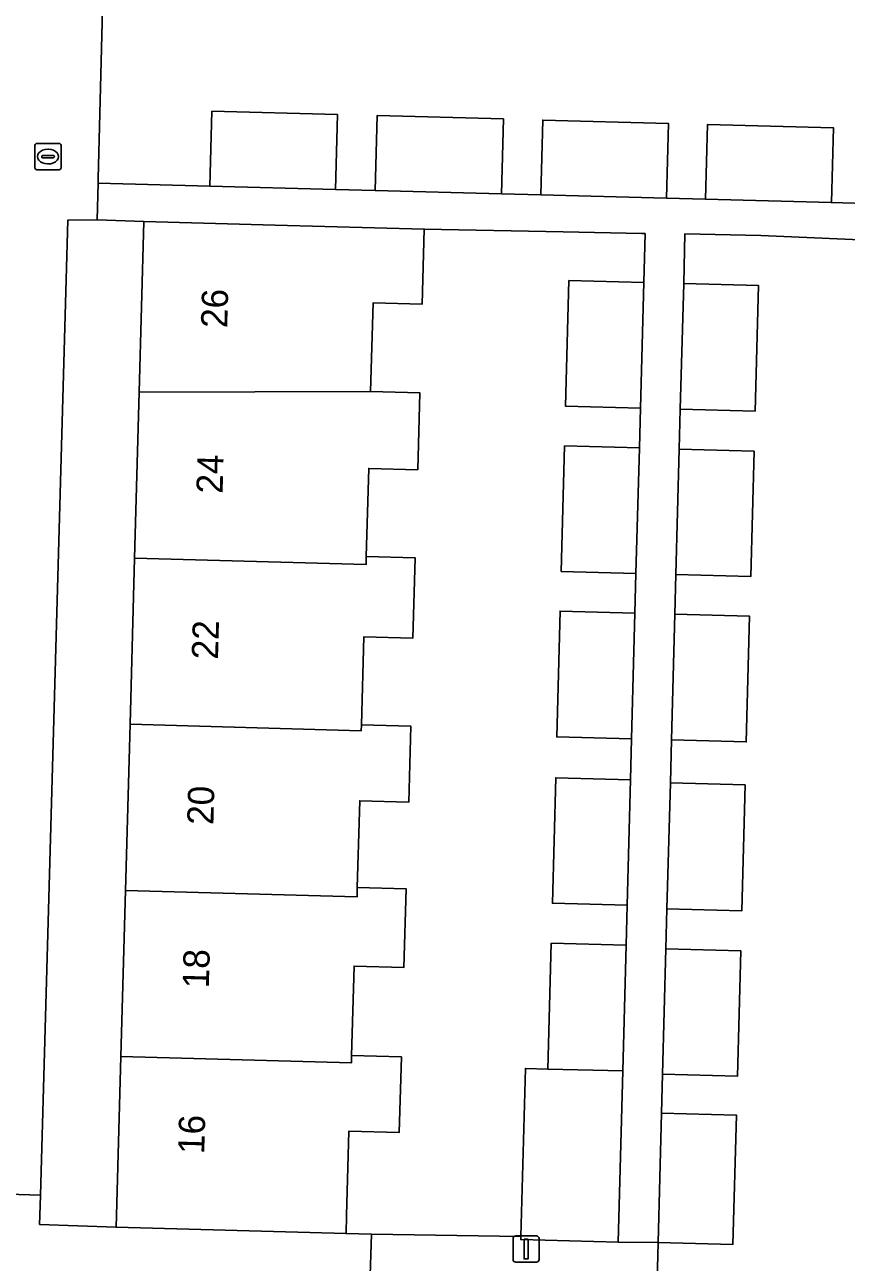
# Model space of a CAD drawing. Extents: x 162082 to 163401, y 388089 to 388636.
# Drawn here: x 162530.44 to 162561.73, y 388248.21 to 388295.36 of the extents above; entities that cross this region are included whole.
import ezdxf

# ---------------------------------------------------------------- set-up
doc = ezdxf.new("R2010")
doc.units = 0
for name, color, linetype in [('IMGEO_Erf', 7, 'Continuous'), ('IMGEO_Lichtmast', 7, 'Continuous'), ('IMGEO_Muur', 7, 'Continuous'), ('IMGEO_Pand', 7, 'Continuous'), ('IMGEO_Pand_nummerreeks', 7, 'Continuous'), ('IMGEO_Rijbaan_lokaal_open', 7, 'Continuous'), ('IMGEO_Rioolput', 7, 'Continuous'), ('IMGEO_Voetpad_open', 7, 'Continuous')]:
    doc.layers.add(name, color=color, linetype=linetype)

msp = doc.modelspace()

# ---------------------------------------------------------------- linework, layer by layer
at = {"layer": 'IMGEO_Erf'}
for points in [[(162533.487, 388299.428), (162533.238, 388289.496), (162533.234, 388289.327), (162537.498, 388289.214), (162537.574, 388292.063), (162542.353, 388291.935), (162542.278, 388289.086), (162543.785, 388289.046), (162543.86, 388291.895), (162548.673, 388291.768), (162548.598, 388288.919), (162550.1, 388288.879), (162550.176, 388291.728), (162554.961, 388291.6), (162554.885, 388288.751), (162556.378, 388288.712), (162556.454, 388291.561), (162561.247, 388291.433), (162561.171, 388288.584), (162562.91, 388288.538)], [(162563.431, 388287.118), (162558.479, 388287.33), (162555.592, 388287.396), (162555.542, 388285.5), (162558.391, 388285.424), (162558.263, 388280.639), (162555.414, 388280.715), (162555.373, 388279.184), (162558.222, 388279.108), (162558.095, 388274.332), (162555.246, 388274.408), (162555.206, 388272.898), (162558.055, 388272.822), (162557.927, 388268.039), (162555.078, 388268.115), (162555.034, 388266.473), (162557.883, 388266.397), (162557.755, 388261.598), (162554.906, 388261.674), (162554.866, 388260.157), (162557.715, 388260.081), (162557.587, 388255.298), (162554.738, 388255.374), (162554.699, 388253.897), (162557.548, 388253.821), (162557.416, 388248.896), (162554.567, 388248.972), (162554.502, 388246.538)]]:
    msp.add_lwpolyline(points, dxfattribs=at)
for points in [[(162534.627, 388275.035), (162534.803, 388281.363), (162534.984, 388287.867), (162533.199, 388287.922), (162532.089, 388287.917), (162531.036, 388250.765), (162531.014, 388250), (162531.004, 388249.658), (162533.918, 388249.549), (162533.931, 388250), (162534.099, 388256.052), (162534.275, 388262.38), (162534.451, 388268.708)], [(162553.685, 388272.947), (162553.725, 388274.453), (162550.876, 388274.529), (162551.004, 388279.31), (162553.853, 388279.234), (162553.893, 388280.746), (162551.044, 388280.822), (162551.172, 388285.613), (162554.021, 388285.537), (162554.071, 388287.401), (162553.952, 388287.404), (162550.954, 388287.473), (162545.658, 388287.57), (162545.578, 388284.71), (162543.709, 388284.762), (162543.615, 388281.385), (162545.494, 388281.333), (162545.413, 388278.406), (162543.544, 388278.458), (162543.451, 388275.105), (162545.311, 388275.053), (162545.226, 388271.995), (162543.36, 388272.046), (162543.266, 388268.688), (162545.15, 388268.636), (162545.07, 388265.741), (162543.2, 388265.793), (162543.109, 388262.491), (162544.967, 388262.44), (162544.884, 388259.443), (162542.986, 388259.496), (162542.891, 388256.087), (162544.788, 388256.034), (162544.708, 388253.158), (162542.79, 388253.211), (162542.7, 388250), (162542.681, 388249.305), (162543.645, 388249.286), (162549.338, 388249.19), (162549.511, 388255.598), (162550.371, 388255.576), (162550.499, 388260.364), (162553.347, 388260.288), (162553.388, 388261.813), (162550.539, 388261.889), (162550.667, 388266.674), (162553.516, 388266.598), (162553.557, 388268.149), (162550.708, 388268.225), (162550.836, 388273.023)]]:
    msp.add_lwpolyline(points, close=True, dxfattribs=at)
at = {"layer": 'IMGEO_Lichtmast'}
for p, q in [((162549.044, 388248.317), (162549.044, 388249.117)), ((162549.044, 388249.117), (162549.044, 388248.317)), ((162549.144, 388249.217), (162549.934, 388249.217)), ((162549.934, 388249.217), (162549.144, 388249.217)), ((162550.034, 388249.117), (162550.034, 388248.317)), ((162550.034, 388248.317), (162550.034, 388249.117)), ((162549.934, 388248.217), (162549.144, 388248.217)), ((162549.144, 388248.217), (162549.934, 388248.217))]:
    msp.add_line(p, q, dxfattribs=at)
msp.add_lwpolyline([(162549.464, 388249.092), (162549.614, 388249.092), (162549.614, 388248.342), (162549.464, 388248.342), (162549.464, 388249.092)], dxfattribs=at)
for centre, start, end in [((162549.144, 388249.117), 90, 180), ((162549.144, 388249.117), 90, 180), ((162549.934, 388249.117), 0, 90), ((162549.934, 388249.117), 360, 90), ((162549.144, 388248.317), 180, 270), ((162549.144, 388248.317), 180, 270), ((162549.934, 388248.317), 270, 0), ((162549.934, 388248.317), 270, 0)]:
    msp.add_arc(centre, 0.1, start, end, dxfattribs=at)
at = {"layer": 'IMGEO_Muur'}
msp.add_lwpolyline([(162533.238, 388289.496), (162533.487, 388299.428)], dxfattribs=at)
at = {"layer": 'IMGEO_Pand'}
for points in [[(162537.498, 388289.214), (162542.278, 388289.086), (162542.353, 388291.935), (162537.574, 388292.063)], [(162543.785, 388289.046), (162548.598, 388288.919), (162548.673, 388291.768), (162543.86, 388291.895)], [(162550.1, 388288.879), (162554.885, 388288.751), (162554.961, 388291.6), (162550.176, 388291.728)], [(162556.378, 388288.712), (162561.171, 388288.584), (162561.247, 388291.433), (162556.454, 388291.561)], [(162534.803, 388281.363), (162543.615, 388281.385), (162543.709, 388284.762), (162545.578, 388284.71), (162545.658, 388287.57), (162539.983, 388287.728), (162534.984, 388287.867)], [(162554.021, 388285.537), (162551.172, 388285.613), (162551.044, 388280.822), (162553.893, 388280.746)], [(162555.542, 388285.5), (162555.414, 388280.715), (162558.263, 388280.639), (162558.391, 388285.424)], [(162534.627, 388275.035), (162543.442, 388274.789), (162543.451, 388275.105), (162543.544, 388278.458), (162545.413, 388278.406), (162545.494, 388281.333), (162543.615, 388281.385), (162534.803, 388281.363)], [(162553.853, 388279.234), (162551.004, 388279.31), (162550.876, 388274.529), (162553.725, 388274.453)], [(162555.373, 388279.184), (162555.246, 388274.408), (162558.095, 388274.332), (162558.222, 388279.108)], [(162534.627, 388275.035), (162534.451, 388268.708), (162543.26, 388268.463), (162543.266, 388268.688), (162543.36, 388272.046), (162545.226, 388271.995), (162545.311, 388275.053), (162543.451, 388275.105), (162543.442, 388274.789)], [(162553.685, 388272.947), (162550.836, 388273.023), (162550.708, 388268.225), (162553.557, 388268.149)], [(162555.206, 388272.898), (162555.078, 388268.115), (162557.927, 388268.039), (162558.055, 388272.822)], [(162534.451, 388268.708), (162534.275, 388262.38), (162543.099, 388262.134), (162543.109, 388262.491), (162543.2, 388265.793), (162545.07, 388265.741), (162545.15, 388268.636), (162543.266, 388268.688), (162543.26, 388268.463)], [(162553.516, 388266.598), (162550.667, 388266.674), (162550.539, 388261.889), (162553.388, 388261.813)], [(162555.034, 388266.473), (162554.906, 388261.674), (162557.755, 388261.598), (162557.883, 388266.397)], [(162534.099, 388256.052), (162542.883, 388255.807), (162542.891, 388256.087), (162542.986, 388259.496), (162544.884, 388259.443), (162544.967, 388262.44), (162543.109, 388262.491), (162543.099, 388262.134), (162534.275, 388262.38)], [(162553.347, 388260.288), (162550.499, 388260.364), (162550.371, 388255.576), (162553.22, 388255.502)], [(162554.866, 388260.157), (162554.738, 388255.374), (162557.587, 388255.298), (162557.715, 388260.081)], [(162534.099, 388256.052), (162533.931, 388250), (162533.918, 388249.549), (162542.681, 388249.305), (162542.7, 388250), (162542.79, 388253.211), (162544.708, 388253.158), (162544.788, 388256.034), (162542.891, 388256.087), (162542.883, 388255.807)], [(162553.22, 388255.502), (162550.371, 388255.576), (162549.511, 388255.598), (162549.338, 388249.19), (162549.335, 388249.08), (162553.046, 388248.985)], [(162554.699, 388253.897), (162554.567, 388248.972), (162557.416, 388248.896), (162557.548, 388253.821)]]:
    msp.add_lwpolyline(points, close=True, dxfattribs=at)
at = {"layer": 'IMGEO_Rijbaan_lokaal_open'}
msp.add_lwpolyline([(162554.502, 388246.538), (162554.567, 388248.972), (162553.046, 388248.985), (162549.335, 388249.08), (162549.338, 388249.19), (162543.645, 388249.286), (162543.583, 388247.323)], dxfattribs=at)
at = {"layer": 'IMGEO_Rioolput'}
for p, q in [((162530.827, 388289.909), (162530.827, 388290.761)), ((162530.902, 388290.835), (162531.754, 388290.835)), ((162531.828, 388290.761), (162531.828, 388289.909)), ((162531.086, 388290.329), (162531.086, 388290.341)), ((162531.524, 388290.292), (162531.126, 388290.292)), ((162531.129, 388290.378), (162531.527, 388290.378)), ((162531.315, 388290.615), (162531.34, 388290.615)), ((162531.57, 388290.341), (162531.57, 388290.329)), ((162531.754, 388289.835), (162530.902, 388289.835)), ((162531.338, 388290.055), (162531.313, 388290.055))]:
    msp.add_line(p, q, dxfattribs=at)
for points in [[(162530.827, 388289.909), (162530.827, 388290.761)], [(162530.902, 388290.835), (162531.754, 388290.835)], [(162531.828, 388290.761), (162531.828, 388289.909)], [(162531.754, 388289.835), (162530.902, 388289.835)]]:
    msp.add_lwpolyline(points, dxfattribs=at)
for centre, radius, start, end in [((162530.904, 388290.759), 0.0765, 91.552, 178.448), ((162530.904, 388290.759), 0.0765, 91.552, 178.448), ((162531.752, 388290.759), 0.0765, 1.552, 88.448), ((162531.752, 388290.759), 0.0765, 1.552, 88.448), ((162531.126, 388290.338), 0.0403, 85.8775, 175.7526), ((162531.123, 388290.328), 0.0366, 178.938, 274.7102), ((162531.527, 388290.335), 0.043, 264.8664, 352.4533), ((162531.531, 388290.34), 0.0386, 1.7309, 96.639), ((162530.904, 388289.911), 0.0765, 181.552, 268.448), ((162530.904, 388289.911), 0.0765, 181.552, 268.448), ((162531.752, 388289.911), 0.0765, 271.552, 358.448), ((162531.752, 388289.911), 0.0765, 271.552, 358.448)]:
    msp.add_arc(centre, radius, start, end, dxfattribs=at)
for centre, major_axis, ratio, start_param, end_param in [((162531.314, 388290.335), (-0.387, 0.002), 0.722429, 4.712389, 7.853982), ((162531.339, 388290.335), (-0.39, 0.002), 0.717154, 1.570796, 4.712389)]:
    msp.add_ellipse(centre, major_axis=major_axis, ratio=ratio, start_param=start_param, end_param=end_param, dxfattribs=at)
at = {"layer": 'IMGEO_Voetpad_open'}
msp.add_lwpolyline([(162532.089, 388287.917), (162533.199, 388287.922), (162533.234, 388289.327), (162533.238, 388289.496), (162533.487, 388299.428), (162533.741, 388308.189), (162533.867, 388312.548), (162530.329, 388312.664), (162530.241, 388310.204), (162530.19, 388308.231), (162529.966, 388299.491), (162529.848, 388294.123), (162529.771, 388291.337), (162528.873, 388269.279), (162528.684, 388263.269), (162528.43, 388263.268), (162528.15, 388250.86), (162531.036, 388250.765)], close=True, dxfattribs=at)
for points in [[(162562.91, 388288.538), (162561.171, 388288.584), (162556.378, 388288.712), (162554.885, 388288.751), (162550.1, 388288.879), (162548.598, 388288.919), (162543.785, 388289.046), (162542.278, 388289.086), (162537.498, 388289.214), (162533.234, 388289.327), (162533.199, 388287.922), (162534.984, 388287.867), (162539.983, 388287.728), (162545.658, 388287.57), (162550.954, 388287.473), (162553.952, 388287.404), (162554.071, 388287.401), (162554.021, 388285.537), (162553.893, 388280.746), (162553.853, 388279.234), (162553.725, 388274.453), (162553.685, 388272.947), (162553.557, 388268.149), (162553.516, 388266.598), (162553.388, 388261.813), (162553.347, 388260.288), (162553.22, 388255.502), (162553.046, 388248.985), (162554.567, 388248.972), (162554.699, 388253.897), (162554.738, 388255.374), (162554.866, 388260.157), (162554.906, 388261.674), (162555.034, 388266.473), (162555.078, 388268.115), (162555.206, 388272.898), (162555.246, 388274.408), (162555.373, 388279.184), (162555.414, 388280.715), (162555.542, 388285.5), (162555.592, 388287.396), (162558.479, 388287.33), (162563.431, 388287.118)], [(162521.64, 388248.207), (162523.434, 388248.211), (162523.429, 388247.973), (162533.845, 388247.644), (162538.826, 388247.474), (162543.583, 388247.323), (162543.645, 388249.286), (162542.681, 388249.305), (162533.918, 388249.549), (162531.004, 388249.658), (162531.014, 388250), (162531.036, 388250.765), (162528.15, 388250.86), (162523.708, 388250.998), (162520.97, 388251.082)]]:
    msp.add_lwpolyline(points, dxfattribs=at)

# ---------------------------------------------------------------- texts
at = {"layer": 'IMGEO_Pand_nummerreeks'}
for s, p in [('26', (162538.152, 388283.794)), ('24', (162537.977, 388277.483)), ('22', (162537.801, 388271.168)), ('20', (162537.626, 388264.863)), ('18', (162537.452, 388258.643)), ('16', (162537.277, 388252.329))]:
    msp.add_text(s, height=1, rotation=88.4071, dxfattribs=at).set_placement(p)

doc.saveas('drawing.dxf')
